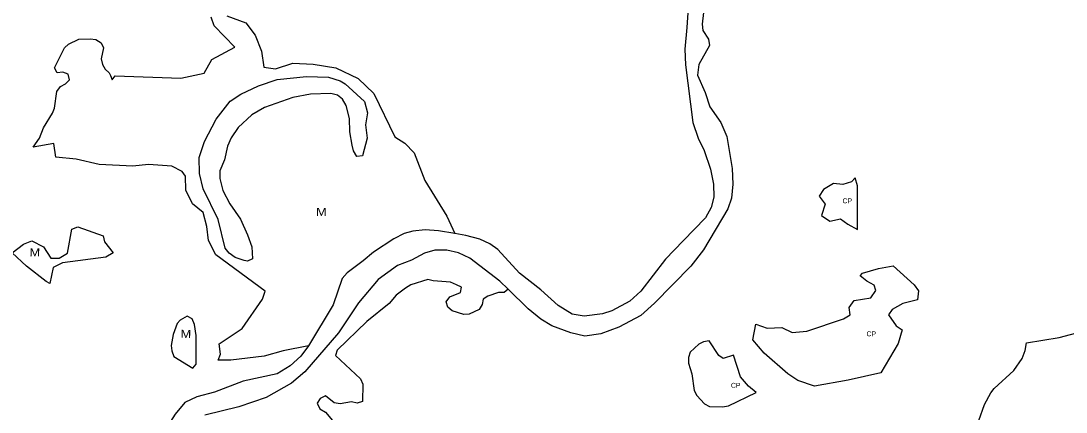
# Model space of a CAD drawing. Extents: x 713589 to 726391, y 7177764 to 7191819.
# Drawn here: x 717458 to 718817, y 7181963 to 7182472 of the extents above; entities that cross this region are included whole.
import ezdxf
from ezdxf.enums import TextEntityAlignment as Align

# ---------------------------------------------------------------- set-up
doc = ezdxf.new("R2010")
doc.units = 0
doc.header["$LTSCALE"] = 2.6
doc.layers.add('63', color=7, linetype='Continuous', lineweight=25)

msp = doc.modelspace()

# ---------------------------------------------------------------- linework, layer by layer
at = {"layer": '63'}
for points in [[(717832.29, 7182049.62), (717799.27, 7182043.35), (717774.59, 7182036.11), (717731.48, 7182030.86), (717714.7, 7182031.19), (717717.99, 7182038.76), (717716.02, 7182052.25), (717745.97, 7182071.99), (717772.3, 7182110.15), (717775.92, 7182120.68), (717711.76, 7182167.75), (717702.22, 7182186.51), (717699.92, 7182204.61), (717695.32, 7182223.04), (717681.5, 7182234.23), (717672.95, 7182252), (717672.29, 7182270.43), (717668.01, 7182276.35), (717654.52, 7182283.27), (717624.25, 7182285.25), (717603.85, 7182283.28), (717560.08, 7182285.26), (717530.14, 7182292.5), (717503.81, 7182295.14), (717501.14, 7182312.52), (717474.62, 7182308.1), (717482.76, 7182319.49), (717488.02, 7182332.99), (717499.54, 7182352.07), (717502.18, 7182358.65), (717505.14, 7182380.37), (717509.75, 7182386.95), (717516.66, 7182390.24), (717521.6, 7182395.5), (717519.95, 7182402.74), (717513.04, 7182405.38), (717505.48, 7182404.72), (717502.19, 7182410.97), (717515.02, 7182436.97), (717520.29, 7182441.9), (717533.78, 7182448.15), (717548.59, 7182448.81), (717555.83, 7182447.82), (717562.74, 7182443.54), (717566.03, 7182436.96), (717562.74, 7182422.81), (717564.38, 7182415.57), (717568, 7182409.32), (717573.26, 7182404.71), (717574.75, 7182401.02), (717576.9, 7182395.65), (717581.14, 7182400.79), (717666.39, 7182397.78), (717696.67, 7182404.36), (717706.54, 7182421.8), (717736.49, 7182437.92), (717709.84, 7182465.89), (717705.89, 7182476.75)], [(717726.3, 7182478.72), (717750.64, 7182469.5), (717763.15, 7182453.71), (717771.37, 7182432.97), (717774.33, 7182411.91), (717789.46, 7182409.61), (717811.84, 7182417.17), (717838.5, 7182415.85), (717867.78, 7182410.91), (717896.74, 7182397.08), (717917.14, 7182377.66), (717944.44, 7182321.39), (717957.6, 7182313.16), (717969.78, 7182300.65), (717983.26, 7182264.78), (718012.21, 7182218.38), (718022.39, 7182195.55)], [(718325.59, 7182489.15), (718323.77, 7182463.72), (718321.31, 7182435.19), (718322.34, 7182415.2), (718331.92, 7182340.02), (718338.56, 7182319.64), (718346.37, 7182303.62), (718354.64, 7182279.35), (718358.73, 7182259.88), (718358.92, 7182242.96), (718355.56, 7182229.37), (718348.29, 7182216), (718319.29, 7182186.08), (718296.33, 7182162.35), (718264.27, 7182120.58), (718249.97, 7182107.87), (718226.36, 7182095.19), (718214.43, 7182091.27), (718190.35, 7182088.19), (718174.9, 7182090.96), (718156.76, 7182102.25), (718134.08, 7182122.41), (718106.29, 7182144.14), (718078.48, 7182174.83), (718068.14, 7182182.11), (718054.85, 7182188.35), (718036.68, 7182193.21), (718022.39, 7182195.55)], [(718345.58, 7182482.92), (718343.99, 7182467.69), (718344.87, 7182459.71), (718352.29, 7182448.15), (718353.58, 7182440.14), (718339.35, 7182415.5), (718338.03, 7182401.42), (718347.75, 7182378.91), (718353.67, 7182360.5), (718368.16, 7182340.05), (718375.73, 7182321.75), (718382.95, 7182280.12), (718383.58, 7182259.89), (718381.81, 7182241.52), (718377.45, 7182227.91), (718345.41, 7182174.25), (718329.09, 7182153.29), (718282.09, 7182105.18), (718264.36, 7182089.22), (718235.46, 7182073.99), (718212.14, 7182065.05), (718191.3, 7182062.34), (718173.15, 7182066.41), (718148.71, 7182075.82), (718134, 7182084.51), (718117.84, 7182097.96), (718091.82, 7182123.24)], [(718022.39, 7182195.55), (718001.22, 7182199.02), (717983.8, 7182200.41), (717967.84, 7182198.92), (717956.72, 7182195.64), (717943.12, 7182188.76), (717916.57, 7182171.31), (717903.45, 7182159.97), (717882.48, 7182144.62), (717875.99, 7182137.05), (717864.52, 7182103.14), (717832.29, 7182049.62)], [(718091.82, 7182123.24), (718081.03, 7182133.72), (718041.86, 7182163.7), (718027.21, 7182170.42), (718011.93, 7182174.19), (717996.4, 7182174.1), (717983.01, 7182170.13), (717966.04, 7182161.12), (717947.94, 7182153.97), (717922.59, 7182135.76), (717897.06, 7182105.66), (717871.44, 7182066.56), (717827.28, 7182015.85), (717810.35, 7182001.3), (717777.11, 7181982.36), (717741.68, 7181970.44), (717697.69, 7181959.42)], [(718091.82, 7182123.24), (718086.59, 7182119.13), (718079.35, 7182118.8), (718065.2, 7182114.2), (718059.27, 7182110.25), (718057.95, 7182103.34), (718054, 7182096.76), (718041.17, 7182090.84), (718033.93, 7182090.51), (718019.12, 7182095.12), (718013.2, 7182099.73), (718011.23, 7182106.64), (718015.84, 7182113.22), (718029.66, 7182118.81), (718030.97, 7182125.72), (718024.72, 7182129.01), (718016.83, 7182132.31), (717994.45, 7182133.96), (717987.21, 7182135.93), (717965.16, 7182129.02), (717958.25, 7182124.75), (717946.4, 7182115.54), (717937.19, 7182104.68), (717908.22, 7182081.32), (717869.72, 7182044.14), (717867.41, 7182037.23), (717899.98, 7182006.62), (717902.94, 7181999.71), (717902.28, 7181977.33), (717895.37, 7181975.03), (717888.13, 7181977.01), (717873.32, 7181974.05), (717865.76, 7181975.69), (717854.24, 7181984.58), (717847.33, 7181981.29), (717843.71, 7181975.04), (717847, 7181967.8), (717854.24, 7181963.52), (717863.45, 7181952.66)], [(718703.48, 7181952.5), (718710.68, 7181973.51), (718718.96, 7181988.59), (718723.32, 7181994.27), (718748.89, 7182017.43), (718759.77, 7182033.3), (718763.49, 7182043.73), (718765.41, 7182053.66), (718807.77, 7182060.29), (718837.11, 7182068.42)], [(717832.29, 7182049.62), (717822.19, 7182036.26), (717808.38, 7182023.48), (717791.72, 7182013.22), (717747.47, 7182003.66), (717710.05, 7181989.56), (717687, 7181983.32), (717671.45, 7181976), (717658.76, 7181961.01), (717649.2, 7181945.23)]]:
    msp.add_lwpolyline(points, dxfattribs=at)
for points in [[(717886.02, 7182327.97), (717885.48, 7182345.36), (717881.27, 7182362.19), (717876.64, 7182370.24), (717869.91, 7182375.39), (717861.46, 7182377.59), (717834.94, 7182376.84), (717811.8, 7182372.61), (717774.99, 7182359.36), (717758.48, 7182350.01), (717740.99, 7182333.46), (717731.93, 7182319.97), (717726.91, 7182309.27), (717723.13, 7182291.37), (717717.23, 7182277.12), (717716.91, 7182267.17), (717720.8, 7182251.48), (717730.18, 7182234.48), (717743.84, 7182214.47), (717752.99, 7182194.17), (717758.82, 7182178.22), (717759.65, 7182162.89), (717752.84, 7182159.83), (717748.68, 7182160.59), (717736.75, 7182164.59), (717729.21, 7182170), (717724.17, 7182176.73), (717714.94, 7182214.03), (717695.16, 7182253.63), (717690.51, 7182273.81), (717690.1, 7182294.41), (717697.18, 7182315.49), (717712.32, 7182344.36), (717730.49, 7182367.62), (717744.31, 7182376.81), (717767.11, 7182387.48), (717791.7, 7182395.87), (717829.73, 7182399.96), (717858.09, 7182398.75), (717873.32, 7182393.97), (717879.85, 7182390.3), (717905.25, 7182367.1), (717908.92, 7182352.58), (717906.51, 7182337.06), (717908.59, 7182319.84), (717902.49, 7182296.53), (717895.05, 7182295.87), (717890.84, 7182302.97), (717888.9, 7182310.61)], [(718537.99, 7182262.92), (718526.8, 7182259.3), (718514.62, 7182260.62), (718501.46, 7182253.06), (718495.86, 7182244.17), (718503.76, 7182233.97), (718498.82, 7182219.16), (718509.68, 7182211.92), (718523.83, 7182214.88), (718533.04, 7182207.64), (718545.87, 7182200.73), (718545.55, 7182257.66), (718542.92, 7182267.86)], [(717565.33, 7182192.46), (717567.3, 7182184.89), (717578.49, 7182170.74), (717568.94, 7182164.82), (717512.67, 7182157.59), (717500.5, 7182151.34), (717495.89, 7182130.77), (717491.39, 7182133.44), (717465.63, 7182153.19), (717447.32, 7182170.61), (717462, 7182181.62), (717472.86, 7182186.22), (717487.67, 7182178.32), (717497.21, 7182163.84), (717508.4, 7182163.84), (717519.26, 7182170.09), (717524.53, 7182201.35), (717532.42, 7182204.31)], [(718625.16, 7182121.08), (718623.85, 7182109.56), (718604.76, 7182104.63), (718590.61, 7182097.06), (718586, 7182089.82), (718595.87, 7182075.67), (718603.99, 7182070.52), (718598.5, 7182052.64), (718576.06, 7182014.63), (718533.66, 7182004.93), (718489.9, 7181997.37), (718468.18, 7182004.61), (718455.02, 7182013.17), (718424.42, 7182040.16), (718409.94, 7182057.61), (718413.43, 7182077.9), (718428.37, 7182072.74), (718447.46, 7182073.39), (718460.95, 7182066.81), (718480.04, 7182068.78), (718527.75, 7182084.9), (718536.31, 7182089.83), (718535, 7182099.38), (718541.25, 7182108.59), (718563.3, 7182111.87), (718569.55, 7182121.75), (718567.58, 7182128.33), (718558.04, 7182133.59), (718549.15, 7182140.84), (718552.44, 7182144.13), (718573.18, 7182150.37), (718591.93, 7182153.66), (718619.57, 7182128.98)], [(717681.79, 7182020.66), (717686.4, 7182025.93), (717686.4, 7182063.11), (717684.1, 7182077.59), (717681.14, 7182084.83), (717674.56, 7182088.12), (717665.3, 7182083.18), (717661.4, 7182078.58), (717656.46, 7182064.43), (717653.82, 7182050.28), (717654.81, 7182043.05), (717657.44, 7182035.81)], [(718333.54, 7181991.52), (718336.83, 7181985.27), (718347.03, 7181974.08), (718353.61, 7181970.79), (718370.39, 7181970.46), (718378.29, 7181971.77), (718414.01, 7181988.94), (718404.25, 7181997.07), (718393.7, 7182009.28), (718384.8, 7182037.31), (718371.06, 7182032.98), (718365.47, 7182037.26), (718352.97, 7182056.02), (718345.73, 7182055.03), (718339.48, 7182051.74), (718328.29, 7182041.54), (718325.98, 7182034.31), (718325.98, 7182027.07), (718330.58, 7182013.24)]]:
    msp.add_lwpolyline(points, close=True, dxfattribs=at)

# ---------------------------------------------------------------- texts
for s, height, width, p in [('CP', 6.4, 1.05, (718532.46, 7182234.96)), ('M', 10.4, 1.2, (717848.91, 7182218.55)), ('M', 10.4, 1.2, (717476.53, 7182166.04)), ('M', 10.4, 1.2, (717672.84, 7182059.98)), ('CP', 6.4, 1.05, (718563.63, 7182062.06)), ('CP', 6.4, 1.05, (718387.43, 7181995.07))]:
    msp.add_text(s, height=height, rotation=359.062, dxfattribs=dict(at, width=width)).set_placement(p, align=Align.CENTER)

doc.saveas('drawing.dxf')
